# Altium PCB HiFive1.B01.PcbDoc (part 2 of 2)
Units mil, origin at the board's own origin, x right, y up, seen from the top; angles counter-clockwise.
Board outline 2700 x 2100 mil, 2 copper layers (Top Layer, Bottom Layer), stack 61 mil thick; 112 components, 78 nets, 451 pads, 247 vias.
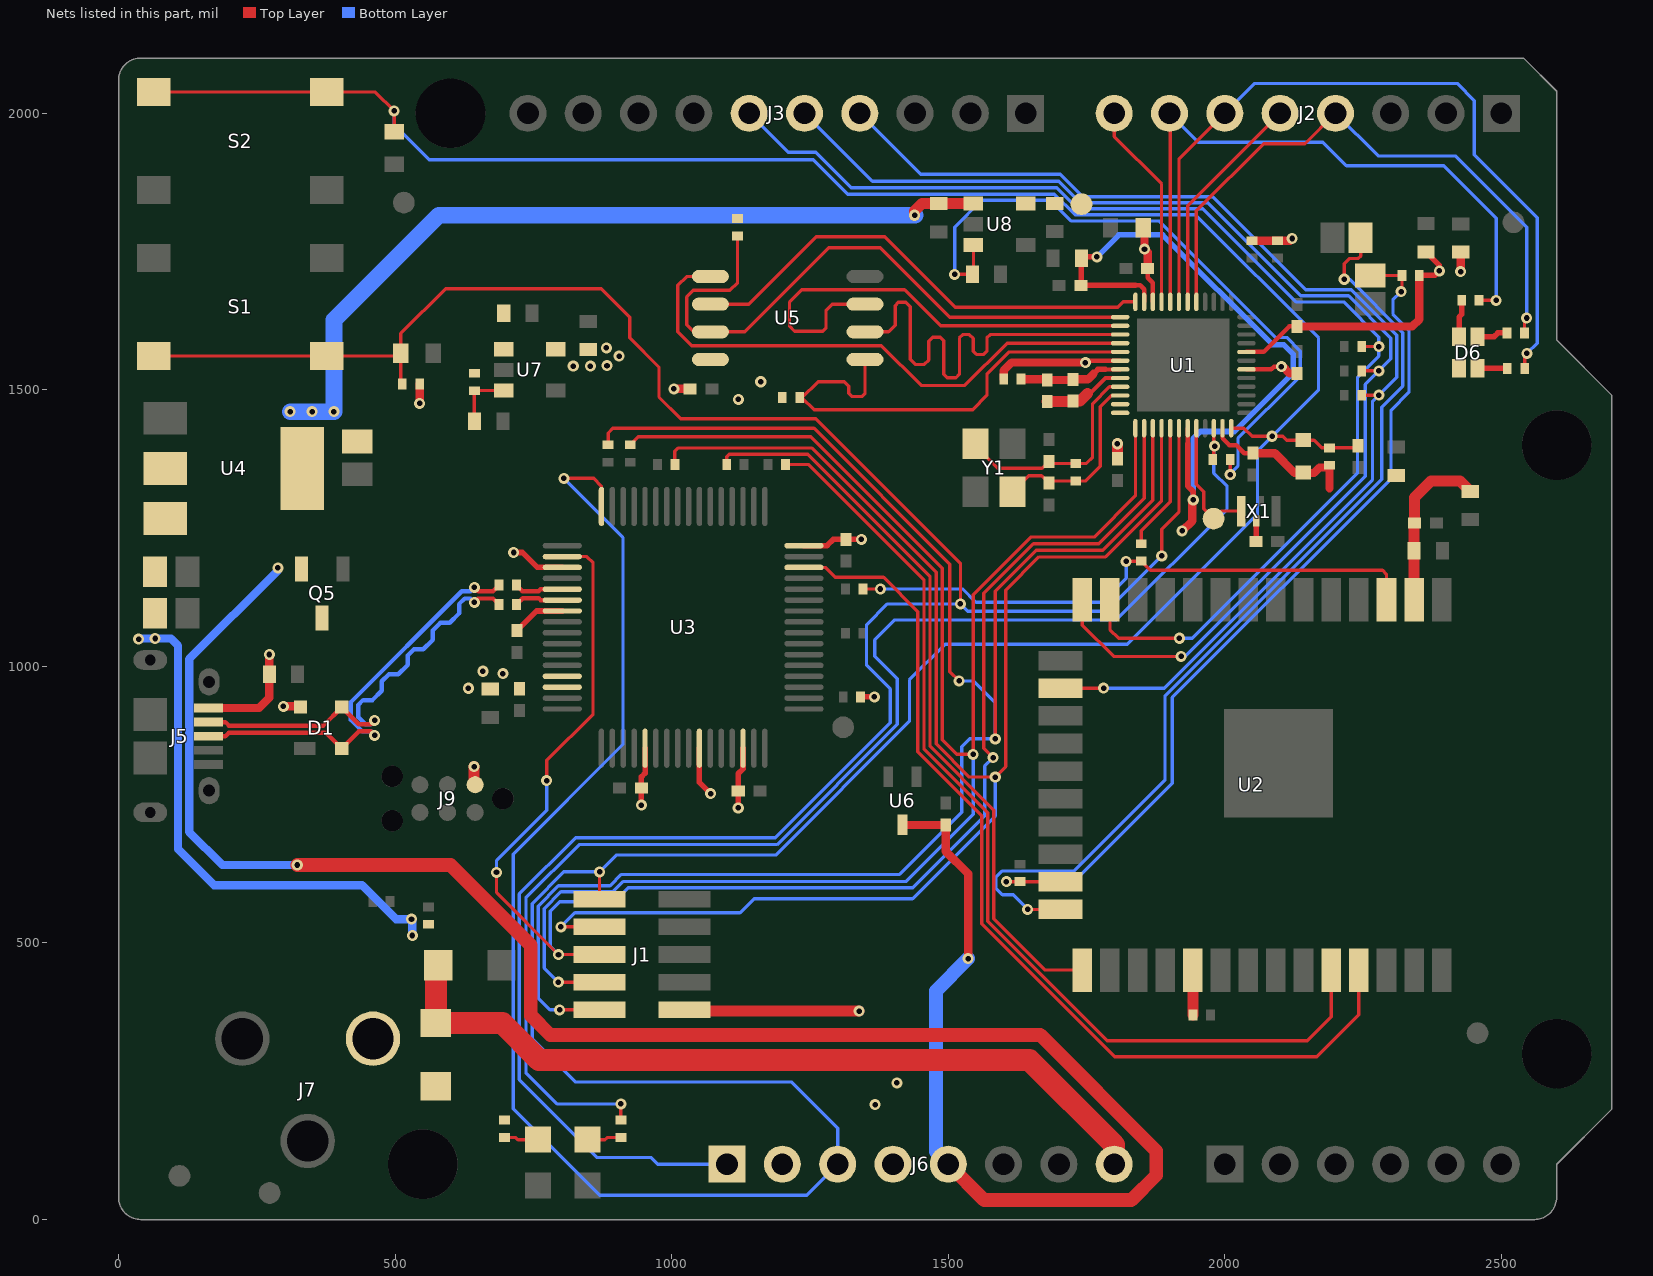
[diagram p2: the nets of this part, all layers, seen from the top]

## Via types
v1: diameter 20, hole 10, Top Layer to Bottom Layer, tented both sides, 229 vias
v2: diameter 20, hole 10.1, Top Layer to Bottom Layer, tented both sides, 18 vias

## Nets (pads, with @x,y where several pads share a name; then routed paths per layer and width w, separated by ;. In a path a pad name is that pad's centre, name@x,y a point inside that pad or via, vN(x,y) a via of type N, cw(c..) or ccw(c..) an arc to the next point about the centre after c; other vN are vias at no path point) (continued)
GPIO_19: J2.4 R18.2 U1.41 | length 1112.7
  Top Layer w6: U1.41@1948.62,1659.17 1948.62,1823.62 2070,1945 2145,1945 J2.4@2200,2000 ; R18.2@2541.75,1603 2541.75,1626.06 v1(2545.69,1630)
  Bottom Layer w6: J2.4@2200,2000 2277,1923 2417,1923 2545.69,1794.31 v1(2545.69,1630)
GPIO_20: J2.5 U1.42 | length 410.1
  Top Layer w6: U1.42@1932.87,1659.17 1932.87,1832.87 J2.5@2100,2000
GPIO_21: J2.6 R17.2 U1.43 | length 1401.7
  Top Layer w6: U1.43@1917.13,1659.17 1917.13,1917.13 J2.6@2000,2000 ; R17.2@2542.28,1539 2542.28,1562.06 v1(2546.22,1566)
  Bottom Layer w6: J2.6@2000,2000 2054,2054 2420,2054 2451,2023 2451,1925 2564.69,1811.31 2564.69,1584.46 v1(2546.22,1566)
GPIO_22: J2.7 R19.2 U1.44 | length 1186
  Top Layer w6: J2.7@1900,2000 1901.38,1998.62 U1.44@1901.38,1659.17 ; R19.2@2463.69,1662 v1(2490.69,1662)
  Bottom Layer w6: J2.7@1900,2000 1952,1948 2177,1948 2220,1905 2396,1905 2490.69,1810.31 v1(2490.69,1662)
GPIO_23: J2.8 U1.45 | length 376.3
  Top Layer w6: J2.8@1800,2000 1800,1958 1885.63,1872.37 U1.45@1885.63,1659.17
JTAG_TCK: J1.4 R25.2 U1.13 | length 2996.5
  Top Layer w6: v1(795.17,429.12) J1.4@869.57,429.12 ; R25.2@925,1400.75 939.27,1415.02 1251.73,1415.02 1489,1177.75 1489,867.2 1515.2,841 v1(1545,841) 1545,1130 1649,1234 1764,1234 1838.39,1308.39 U1.13@1838.39,1430.83
  Bottom Layer w6: v1(795.17,429.12) 769.61,454.68 769.61,562.21 799.8,592.4 893.11,592.4 911.81,611.1 1423.14,611.1 1545,732.96 v1(1545,841)
JTAG_TDI: J1.8 R24.2 U1.16 | length 2869.1
  Top Layer w6: v1(799.61,529.12) J1.8@869.57,529.12 ; R24.2@1005.75,1365 1005.75,1389.31 1011.28,1394.84 1253.8,1394.84 1478,1170.64 1478,859.92 1537.92,800 v1(1585,800) 1604,819 1604,1138.09 1663.91,1198 1784.46,1198 1885.63,1299.17 U1.16@1885.63,1430.83
  Bottom Layer w6: v1(799.61,529.12) 825.02,554.52 1123.48,554.52 1148.94,579.98 1435.5,579.98 1585,729.48 v1(1585,800)
JTAG_TDO: J1.6 U1.14 U3.2 | length 2806.2
  Top Layer w6: v1(683.22,627.52) 683.22,591.2 v1(795.3,479.12) J1.6@869.57,479.12 ; v1(773.81,793.39) 774.32,793.91 774.32,830.31 857.69,913.68 857.69,1187.4 846.42,1198.66 U3.2@802.13,1198.66 ; v1(1581,835) 1564,852 1564,1132.03 1653.97,1222 1772,1222 1854.13,1304.13 U1.14@1854.13,1430.83
  Bottom Layer w6: v1(683.22,627.52) 683.22,649.22 773.81,739.81 v1(773.81,793.39) ; v1(795.3,479.12) 780.61,493.81 780.61,557.65 797.71,574.75 895.63,574.75 920.98,600.1 1436.02,600.1 1566,730.08 1566,820 v1(1581,835)
JTAG_TMS: J1.2 R26.2 U1.15 | length 3162.7
  Top Layer w6: v1(797.34,379.12) J1.2@869.57,379.12 ; R26.2@885,1404.69 885,1422.05 893.4,1430.45 1257.32,1430.45 1502.87,1184.91 1502.87,990.46 v1(1519.53,973.81) ; v1(1585,869) 1585,1136.06 1658.94,1210 1779.49,1210 1869.88,1300.4 U1.15@1869.88,1430.83
  Bottom Layer w6: v1(797.34,379.12) 779.81,379.12 758.61,400.32 758.61,566.76 795.24,603.4 888.55,603.4 909.05,623.9 1411.9,623.9 1524.5,736.5 1524.5,854.5 1539,869 v1(1585,869) 1585,933.91 1545.11,973.81 v1(1519.53,973.81)
LF_CLK: TP5.1 U1.20 X1.3 | length 232.3
  Top Layer w6: U1.20@1948.62,1430.83 1948.62,1409 1948.38,1408.76 1948.38,1329.21 1962,1315.59 1962,1284.89 TP5.1@1979.74,1267.16 1993.57,1281 X1.3@2029.5,1281
NetC8_1: C8.1 C9.1 U1.8 | length 149.5
  Top Layer w7: 1752.08,1493.26 1756.43,1493.26 1784.55,1521.38 U1.8@1810.83,1521.38
  Top Layer w20: C8.1@1678.99,1478.69 1724.83,1478.69 C9.1@1725.83,1479.69 1738.51,1479.69 1752.08,1493.26
NetC12_1: C12.1 R4.1 U1.9 Y1.1 | length 402.2
  Top Layer w6: Y1.1@1549.54,1402.31 1549.54,1398.75 1589.7,1358.59 1669.57,1358.59 C12.1@1681.83,1370.84 1685.76,1366.91 R4.1@1730.45,1366.91 1749.33,1366.91 1760.83,1378.4 1760.83,1475.02 1791.43,1505.63 U1.9@1810.83,1505.63
NetC13_1: C13.1 R4.2 U1.10 Y1.3 | length 338
  Top Layer w6: Y1.3@1616.46,1315.69 1645.36,1344.59 1668.71,1344.59 1678.94,1334.36 1679.99,1335.41 R4.2@1730.45,1335.41 1748.67,1335.41 1775,1361.74 1775,1469.4 1795.48,1489.88 U1.10@1810.83,1489.88
NetC21_1: C21.1 R31.1 U7.3 | length 108.7
  Top Layer w6: C21.1@643.41,1443 643.18,1443.22 R31.1@643.18,1498.66 643.29,1498.77 U7.3@696.11,1498.77
NetC22_1: C22.1 R32.2 U8.3 | length 1232.6
  Top Layer w6: v1(1511.46,1708.88) C22.1@1543.58,1708.88 1545.48,1710.78 U8.3@1545.48,1761.99 ; R32.2@2009.75,1374 2009.85,1373.9 v1(2009.85,1346.79)
  Bottom Layer w6: v1(1511.46,1708.88) 1511.46,1794.35 1560.11,1843 1684.17,1843 1721.79,1805.38 1880.73,1805.38 2091.36,1594.75 2111.79,1594.75 2136.47,1570.07 2136.47,1525.38 2129.77,1518.68 ; v1(2009.85,1346.79) 2009.85,1348.35 2023.75,1362.25 2023.75,1412.18 2130.01,1518.44
NetD6_1: D6.1 R19.1 | length 67.9
  Top Layer w10: D6.1@2423.54,1596.09 2423.54,1631.68 2428.25,1636.39 R19.1@2428.25,1662
NetD6_2: D6.2 R18.1 | length 56.1
  Top Layer w10: D6.2@2457,1596.09 2486.84,1596.09 2493.75,1603 R18.1@2510.25,1603
NetD6_3: D6.3 R17.1 | length 49.9
  Top Layer w10: D6.3@2457,1539 R17.1@2506.85,1539
NetD9_2: D9.2 R27.2 | length 61.6
  Top Layer w6: R27.2@698,148.28 718.03,148.28 721.97,144.34 D9.2@758,144.34
NetD10_2: D10.2 R28.2 | length 61.6
  Top Layer w6: D10.2@848,144.34 879.22,144.34 883.16,148.28 R28.2@908,148.28
NetD13_2: D13.2 J7.1
NetR12_2: R12.2 U2.29 | length 81
  Top Layer w20: R12.2@1942.28,370 U2.29@1942.28,450.98
PLL_AVDD: C8.2 C9.2 R1.2 U1.7 | length 183.8
  Top Layer w7: 1784.13,1537.13 U1.7@1810.83,1537.13
  Top Layer w10: 1762.44,1529.11 1770.45,1537.13 1784.13,1537.13
  Top Layer w15: R1.2@1635.51,1519.37 1677.67,1519.37 C8.2@1678.99,1518.06 1724.83,1518.06 C9.2@1725.83,1519.06 1752.38,1519.06 1762.44,1529.11
QSPI_CS0: R13.1 U1.5 U5.1 | length 858.8
  Top Layer w6: U5.1@1349.53,1555 1349.53,1493.53 1344,1488 1326,1488 1320,1494 1320,1507 1312,1515 1264.51,1515 1235.45,1485.93 1257.35,1464.03 1544.03,1464.03 1570,1490 1570,1528.2 1610.42,1568.62 U1.5@1810.83,1568.62
QSPI_DQ0: U1.4 U5.5 | length 1021.3
  Top Layer w6: U5.5@1070,1705 1027,1705 1011,1689 1011,1605 1036,1580 1379,1580 1451,1508 1530,1508 1606.37,1584.37 U1.4@1810.83,1584.37
QSPI_DQ1: U1.3 U5.2 | length 841.2
  Top Layer w6: U5.2@1349.53,1605 1392,1605 1404,1617 1404,1652.48 1409.72,1658.19 1423.41,1658.19 1431,1650.61 1431,1555 1440,1546 1457,1546 1465,1554 1465,1588.12 1472,1595.12 1485.88,1595.12 1492,1589 1492,1528 1498,1522 1514,1522 1520.26,1528.26 1520.26,1593.9 1526.48,1600.12 1537.88,1600.12 1545,1593 1545,1570 1551,1564 1564,1564 1570,1570 1570,1594 1576.12,1600.12 U1.3@1810.83,1600.12
QSPI_DQ2: U1.2 U5.3 | length 857.2
  Top Layer w6: U5.3@1349.53,1655 1290,1655 1279,1644 1279,1612 1273,1606 1222,1606 1213,1615 1213,1659 1235,1681 1421,1681 1486.13,1615.87 U1.2@1810.83,1615.87
QSPI_DQ3: R29.2 U1.1 U5.7 | length 1141.1
  Top Layer w6: R29.2@1119,1778.25 1119,1694 1105,1680 1039,1680 1027,1668 1027,1618 1040,1605 U5.7@1070,1605 1132,1605 1284,1757 1377,1757 1502.39,1631.61 U1.1@1810.83,1631.61
QSPI_SCK: U1.48 U5.6 | length 876
  Top Layer w6: U5.6@1070,1655 1139,1655 1261,1777 1385,1777 1512.76,1649.24 1806.24,1649.24 1816.17,1659.17 U1.48@1838.39,1659.17
RESET: C16.1 D3.2 D5.1 J1.10 J6.3 R5.1 S2.3 S2.4 U1.24 U3.64 | length 7629.2
  Top Layer w6: S2.4@63.5,2038.58 S2.3@376.5,2038.58 464.05,2038.58 v1(498.06,2004.57) D5.1@498.06,1966.92 ; v1(805,1340) 859,1340 872.99,1326.01 U3.64@872.99,1289.21 ; J1.10@869.57,579.12 v1(869.57,628.57) ; U1.24@2011.61,1430.83 2034.54,1430.83 2049.21,1416.16 v1(2085.71,1416.16) 2104.86,1416.16 2112.12,1408.9 2161.3,1408.9 2175.08,1395.12 R5.1@2189.32,1395.12 2236.89,1395.12 C16.1@2240.83,1399.06
  Bottom Layer w6: v1(498.06,2004.57) 498.06,1979.43 561.31,1916.18 1255.82,1916.18 1318,1854 1691.85,1854 1729.47,1816.38 1946.94,1816.38 2169.47,1593.85 2169.47,1499.92 v1(2085.71,1416.16) 2059,1389.45 2059,1275 1824,1040 1494.29,1040 1429.91,975.62 1429.91,900.78 1188.13,659 900,659 v1(869.57,628.57) 804.86,628.57 747.61,571.32 747.61,326.76 825.61,248.76 1216.05,248.76 1300,164.82 J6.3@1300,100 1244,44 869.48,44 713.4,200.08 713.4,660.4 911.85,858.85 911.85,1233.15 v1(805,1340)
SPI_CS2: R10.1 R21.2 SJ1.2 U2.23 | length 1639.3
  Top Layer w6: v1(1605,611) 1605.37,610.63 U2.23@1702.91,610.63 ; SJ1.2@2262.83,1706.96 R10.1@2316.32,1706.96 ; v1(2318.61,1677.5) 2320.25,1679.14 R10.1@2320.25,1706.96
  Bottom Layer w6: v1(1605,611) 1727,611 1905,789 1905,943.88 2300.51,1339.39 2300.51,1463.51 2333,1496 2333,1608.13 2304,1637.13 2304,1662.89 v1(2318.61,1677.5)
SPI_MISO: J3.5 R15.1 U2.14 | length 2240
  Top Layer w6: U2.14@1742.28,1120.28 1742.28,1074.72 1799,1018 v1(1921,1018) ; R15.1@2251.51,1534.37 v1(2278.51,1534.37)
  Bottom Layer w6: J3.5@1240,2000 1362.96,1877.04 1699.92,1877.04 1738.59,1838.38 1969.06,1838.38 2137.44,1670 2223.77,1670 2300,1593.77 2300,1555.86 v1(2278.51,1534.37) 2254,1509.86 2254,1343.79 1928.21,1018 v1(1921,1018)
SPI_MOSI: J3.4 R9.1 U2.16 | length 2164.3
  Top Layer w6: U2.16@1702.91,960.63 v1(1781,960.63) ; R9.1@2251.51,1490.37 v1(2278.51,1490.37)
  Bottom Layer w6: J3.4@1340,2000 1450.02,1889.98 1702.55,1889.98 1743.14,1849.38 1977.86,1849.38 2146.24,1681 2229.02,1681 2311,1599.02 2311,1522.86 v1(2278.51,1490.37) 2267,1478.86 2267,1336.99 1890.64,960.63 v1(1781,960.63)
SPI_SCK: J3.6 R16.1 U2.13 | length 2226.1
  Top Layer w6: U2.13@1792.28,1120.28 1792.28,1066.72 1808,1051 v1(1918,1051) ; R16.1@2251.51,1578.37 v1(2278.51,1578.37)
  Bottom Layer w6: J3.6@1140,2000 1210.5,1929.5 1260.5,1929.5 1324.6,1865.4 1696.01,1865.4 1734.03,1827.38 1960.26,1827.38 2100.41,1687.23 2128.64,1659 2214.97,1659 2278.51,1595.46 v1(2278.51,1578.37) 2278.51,1561.24 2240,1522.73 2240,1350 1941,1051 v1(1918,1051)
USB_D_N: D1.3 J5.2 R2.1 | length 777.6
  Top Layer w8: J5.2@162.5,899.41 193.07,899.41 199.37,893.11 370.24,893.11 D1.3@403.46,926.33 434.36,895.43 455.96,895.43 v1(462.96,902.43) ; v1(643.21,1115.89) 643.21,1116.39 649.71,1122.89 676.88,1122.89 R2.1@687.88,1111.89
  Bottom Layer w8: v1(462.96,902.43) 455.96,895.43 446.1,895.43 433.05,908.48 433.05,930.25 442,939.2 458.99,939.2 475.76,955.97 475.76,972.96 488.8,986 505.79,986 522.56,1002.77 522.56,1019.76 534,1031.2 550.99,1031.2 567.76,1047.97 567.76,1064.96 581.8,1079 598.79,1079 615.56,1095.77 615.56,1112.76 625.69,1122.89 636.21,1122.89 v1(643.21,1115.89)
USB_D_P: D1.2 J5.3 R6.1 | length 778.6
  Top Layer w8: J5.3@162.5,873.82 193.07,873.82 199.37,880.11 374.87,880.11 D1.2@403.46,851.53 434.36,882.43 455.96,882.43 v1(462.96,875.43) ; v1(643.21,1142.89) 650.21,1135.89 676.88,1135.89 R6.1@687.88,1146.89
  Bottom Layer w8: v1(462.96,875.43) 455.96,882.43 440.72,882.43 420.05,903.1 420.05,935.64 620.3,1135.89 636.21,1135.89 v1(643.21,1142.89)
USB_D_R_N: R2.2 U3.6 | length 88.8
  Top Layer w8: R2.2@719.38,1111.89 730.75,1123.26 759.35,1123.26 762.69,1119.92 U3.6@802.13,1119.92
USB_D_R_P: R6.2 U3.5 | length 88.5
  Top Layer w8: R6.2@719.38,1146.89 730,1136.26 759.35,1136.26 762.69,1139.61 U3.5@802.13,1139.61
VBUS: C29.2 D1.4 J5.1 Q5.3 | length 227.2
  Top Layer w15: J5.1@162.5,925 254,925 272.41,943.41 C29.2@272.41,986 v1(272.41,1021.59) ; v1(297.83,927.83) 327.15,927.83 D1.4@328.65,926.33
VDD_1V8: C1.1 C2.2 C3.2 C50.1 R1.1 TP1.1 U1.6 U1.30 U1.46 U8.5 | length 473.4
  Top Layer w8: v1(1747.83,1549.37) 1751.33,1552.87 U1.6@1810.83,1552.87 ; C2.2@1860.51,1719.37 1860.51,1702.87 1869.88,1693.5 U1.46@1869.88,1659.17 ; U1.30@2039.17,1537.13 2084.13,1537.13 2089,1542 v1(2102.47,1542)
  Top Layer w15: R1.1@1600.08,1519.37 1600.08,1534.73 1614.72,1549.37 v1(1747.83,1549.37) ; C1.1@1852.53,1793 1854.83,1790.7 v1(1854.83,1754.37) 1860.51,1748.69 C2.2@1860.51,1719.37 ; v1(2102.47,1542) 2105,1542 2117.32,1529.68 C3.2@2130.83,1529.68
VDD_3V3: C4.2 C5.2 C6.1 C7.1 C10.1 C11.1 C14.1 C15.1 C17.2 C18.2 C19.2 C20.2 C23.2 C24.1 C25.1 C26.1 C27.1 C28.2 C30.1 C47.1 D3.1 D6.4 J1.1 J6.2 J6.4 J9.1 R3.1 R5.2 R7.2 R8.2 R10.2 R13.2 R27.1 R29.1 R33.1 U1.11 U1.12 U1.19 U1.23 U1.32 U1.47 U2.2 U3.3 U3.7 U3.13 U3.14 U3.21 U3.26 U3.30 U3.48 U5.8 U7.5 X1.4 | length 3563.5
  Top Layer w8: 1838,1689 1846.91,1689 1854.13,1681.78 U1.47@1854.13,1659.17 ; 1932.87,1402.62 U1.19@1932.87,1430.83 ; U1.23@1995.87,1430.83 1995.87,1412.71 2008.29,1400.29 2020.71,1400.29 2035.32,1385.68 C5.2@2051,1385.69 ; U1.32@2039.17,1568.62 2070.59,1568.62 2116.66,1614.69 C18.2@2130.83,1614.68
  Top Layer w10: v1(714,1206) 730,1206 757.02,1178.98 U3.3@802.13,1178.98 ; C30.1@720,1064.68 755.55,1100.24 U3.7@802.13,1100.24 ; v1(945,749.22) C27.1@945,780 945,800.22 951.73,806.95 U3.21@951.73,852.2 ; U3.26@1050.16,852.2 1050.16,790.3 v1(1070.24,770.22) ; v1(1120.32,744.08) C26.1@1120.32,775 1120.32,806.08 1128.9,814.66 U3.30@1128.9,852.2 ; U3.48@1239.13,1218.35 1280.73,1218.35 1292.07,1229.68 C24.1@1315,1229.68 v1(1342.95,1229.68) ; R33.1@1341.5,945 v1(1366.31,945) ; v1@1769.22,1740.55 v1(1768.81,1740.55) 1743.14,1740.55 C10.1@1740.59,1738 1740.59,1689.91 C20.2@1739.69,1689 1838,1689 ; 1932.87,1402.62 1932.87,1326.33 1943,1316.2 v1(1943,1301) ; C17.2@2056.31,1226 2057.06,1226.75 X1.4@2057.06,1263.28 ; R10.2@2355.69,1706.96 2379.96,1706.96 v1(2388,1715) 2388,1725.2 C14.1@2363.8,1749.41
  Top Layer w15: v1(544.28,1475.72) R3.1@544.28,1511 ; v1(1003.76,1501.75) 1003.95,1501.93 C23.2@1033.08,1501.93 ; v1(1923,1245) 1941.31,1263.31 1941.31,1299.31 v1(1943,1301) ; R8.2@2049.01,1769.8 R7.2@2095.51,1769.8 2117.8,1769.8 v1(2121.74,1773.74) ; C5.2@2051,1385.69 2090.32,1385.68 2126.16,1349.84 D3.1@2138.56,1349.84 ; C18.2@2130.83,1614.68 2338.78,1614.69 2351.75,1627.65 R10.2@2351.75,1706.96 ; D3.1@2140.83,1347.58 D3.1@2138.56,1349.84 ; 2189.32,1322 2189.32,1359.68 2171.14,1359.68 2161.3,1349.84 D3.1@2138.56,1349.84 ; v1(2426.52,1713.87) C15.1@2426.52,1749.07
  Top Layer w20: v1(642.78,818.89) 642.78,787.99 J9.1@644.65,786.11 ; J1.1@1023.11,379.12 1025.4,376.83 v1(1338.74,376.83) ; C19.2@1805.83,1375.54 v1(1805.83,1402.62) ; U2.2@2342.28,1120.28 C6.1@2342.28,1209.1 2342.28,1258.2 C4.2@2343.18,1259.1 2343.18,1305.18 2373,1335 2425.59,1335 C7.1@2444,1316.59
  Bottom Layer w10: v1(1768.81,1740.55) 1808.47,1780.22 1887.51,1780.22 2085.97,1581.75 2106.4,1581.75 2123.47,1564.69 2123.47,1530.77 2017.48,1424.78 1956.08,1424.78 1943,1411.7 v1(1943,1301)
  other v1: 1367.8,207.86 1407.01,247.17 632.29,960.59 694.87,987.17 658.54,991.27 1120.69,1482.91 1160.97,1514.77 822,1543 853,1543 883,1544 905,1561 882,1576
VDD_5V0: C31.1 C42.1 C45.1 C48.1 J6.5 Q5.2 R31.2 U4.2 U4.4 U6.3 U7.1 U8.1 | length 5306.9
  Top Layer w15: U6.3@1417.21,714.02 1417.81,713.41 C31.1@1495.46,713.41 1495.46,665.75 1535.97,625.23 v1(1535.97,471.74)
  Top Layer w20: v1(1439.3,1815.71) 1439.3,1823.58 1452.44,1836.72 C48.1@1482.63,1836.72 1482.71,1836.8 U8.1@1545.48,1836.8
  Top Layer w25: v1(323,641) 600,641 745.27,495.73 745.27,368.66 780.31,333.61 1666.39,333.61 1876,124 1876,80 1831,35 1565,35 J6.5@1500,100
  Bottom Layer w15: v1(288,1178) 288,1173.5 127.5,1013 127.5,701 187.5,641 v1(323,641)
  Bottom Layer w25: J6.5@1500,100 1477.61,122.39 1477.61,413.38 v1(1535.97,471.74)
  Bottom Layer w30: v1(310,1460.64) v1(349.66,1460.64) v1(389.32,1460.64) 389.32,1626.32 579,1816 v1@1440,1816
VDD_CORE_EN: R28.1 R32.1 U1.22 | length 2420.8
  Top Layer w6: R28.1@908,183.71 v1(908,209) ; R32.1@1980,1378.75 1980,1398.88 1980.12,1399 U1.22@1980.12,1430.83
  Bottom Layer w6: v1(908,209) 792.48,209 736.53,264.95 736.53,582.07 832.45,678 1190.43,678 1407.65,895.22 1407.65,978.07 1367.22,1018.49 1367.22,1047.85 1403.37,1084 1803.5,1084 2004,1284.5 2004,1325.77 1980.12,1349.65 1980.12,1399 1980.62,1398.5 v1(1981.5,1398.5) 1981.5,1398.81 v1@1981.69,1399
VDD_DCIN: C43.1 C44.1 D12.1 D13.1 J6.8 R30.2 U4.3 | length 2414.1
  Top Layer w20: D12.1@575.23,459.37 D12.1@580,464.14
  Top Layer w40: D12.1@575.23,459.37 573.58,457.72 D13.1@573.58,355.19 693.52,355.19 760.15,288.56 1646.44,288.56 1800,135 J6.8@1800,100
  Bottom Layer w15: v1(36,1049.5) 37,1050.5 v1(66,1050.5) 94.5,1050.5 107.5,1037.5 107.5,669.5 172.5,604.5 440,604.5 501.5,543 v1(529.5,543) 531,541.5 v1(531,513.5)
WAKE: D2.1 J6.1 R3.2 S1.1 S1.2 U1.18 | length 4547
  Top Layer w6: S1.2@63.5,1561.42 S1.1@376.5,1561.42 505.42,1561.42 D2.1@510,1566 ; R3.2@508.84,1511 510,1512.16 D2.1@510,1566 ; J6.1@1085.32,114.69 J6.1@1100,100 ; v1(1522,1113) 1522,1186.41 1260.41,1448 1016,1448 977,1487 977,1541 924,1594 924,1631.58 872.56,1683.02 591.02,1683.02 510,1602 D2.1@510,1566 ; v1(1886,1200) 1886,1248 1917.13,1279.13 U1.18@1917.13,1430.83
  Bottom Layer w6: J6.1@1100,100 975,100 963.03,111.97 865.55,111.97 724.4,253.12 724.4,588.61 826.22,690.43 1187.3,690.43 1395.07,898.2 1395.07,959.27 1352.28,1002.05 1352.28,1075.28 1390,1113 v1(1522,1113) 1535,1100 1786,1100 v1(1886,1200)
WF_BOOT_STRAP: R23.2 U2.25 | length 1340.6
  Top Layer w6: R23.2@1099.25,1365 1099.25,1379.44 1103.66,1383.84 1245.74,1383.84 1467,1162.58 1467,855.36 1582.48,739.88 1582.48,543.63 1675.13,450.98 U2.25@1742.28,450.98
WF_INT: SJ2.2 U2.24 | length 1760.8
  Top Layer w6: v1(1643.63,560.63) U2.24@1702.91,560.63 ; v1(2216,1700) 2216,1728 2225.61,1737.61 2241.16,1737.61 2245.59,1742.05 SJ2.2@2245.59,1775
  Bottom Layer w6: v1(1643.63,560.63) 1617.26,587 1598,587 1586,599 1586,618.87 1597.13,630 1727.26,630 1891.75,794.49 1891.75,946.18 2284,1338.44 2284,1468.99 2322,1506.99 2322,1603.57 2225.57,1700 v1(2216,1700)
WF_RESET: R20.2 U1.17 | length 226.5
  Top Layer w6: R20.2@1849,1226 1849,1245.16 1901.38,1297.54 U1.17@1901.38,1430.83
WF_RESET_R: R14.2 R20.1 U2.3 | length 1060
  Top Layer w6: R14.2@1345.75,1140 v1(1377.19,1140) ; v1(1821.74,1190.02) 1845.61,1190.02 R20.1@1847.03,1188.6 ; R20.1@1849,1190.57 1865.57,1174 2285.28,1174 2292.28,1167.01 U2.3@2292.28,1120.28
  Bottom Layer w6: v1(1377.19,1140) 1526,1140 1550,1116 1778,1116 1821.74,1159.74 v1(1821.74,1190.02)
WF_UART_RX: R22.2 U2.34 | length 1815.2
  Top Layer w6: R22.2@1205.75,1365 1248.14,1365 1456,1157.14 1456,850.8 1571.48,735.33 1571.48,539.08 1787.56,323 2149,323 2192.28,366.28 U2.34@2192.28,450.98
WF_UART_TX: U2.35 U3.46 | length 1745.1
  Top Layer w6: U3.46@1239.13,1178.98 1277.32,1178.98 1295.3,1161 1383.06,1161 1445,1099.06 1445,845.84 1560.48,730.36 1560.48,534.52 1801,294 2166,294 2242.28,370.28 U2.35@2242.28,450.98
pads on no net: Designator31.1 Designator32.1 Designator33.1 J3.8 J4.1 J5.4 J5.SH4 J5.SH5 J9.SH1 J9.SH2 J9.SH3 U1. U2. U2.4 U2.5 U2.6 U2.7 U2.8 U2.9 U2.10 U2.11 U2.12 U2.17 U2.18 U2.19 U2.20 U2.21 U2.22 U2.26 U2.27 U2.28 U2.30 U2.31 U2.32 U2.33 U2.36 U2.37 U3.1 U3.8 U3.9 U3.10 U3.11 U3.12 U3.17 U3.18 U3.19 U3.20 U3.23 U3.27 U3.28 U3.29 U3.32 U3.33 U3.35 U3.36 U3.37 U3.38 U3.41 U3.42 U3.43 U3.45 U3.51 U3.52 U3.53 U3.54 U3.55 U3.56 U3.57 U3.58 U3.60 U3.61 U7.4 U8.4 X1.1

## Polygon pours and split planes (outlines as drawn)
VDD_3V3 on Top Layer "Bottom Layer-No Net" (solid, remove dead copper, pour order 63): 1181.63,526.4 1181.63,403.12 1225.61,359.15 1278.27,359.61 1378.61,359.61 1396.74,377.74 1396.74,495.7 1139.46,752.97 1135.19,757.24 1135.19,790.36 1129.33,796.23 1045.95,796.23 1042.93,794.93 1040.78,792.78 1040.78,710.88 1041.09,665.43
NetD13_2 on Top Layer "NETD13_2_L01_P048" (solid, remove dead copper, pour order 48): 514.92,300 546.42,268.49 622.98,268.49 635,256.47 635,170 410,170 410,380 514.92,380
VDD_3V3 on Top Layer "Bottom Layer-No Net" (solid, remove dead copper, pour order 50): 700.33,1001.46 695.68,1006.1 695.68,1044.85 702.09,1051.25 730.13,1051.25 732.4,1053.52 732.4,1075.17 725.81,1081.77 670.55,1081.77 619.73,1030.95 619.73,953.58 626.81,946.49 737.97,946.49 748.32,956.84 836.31,956.84 838.75,959.28 838.48,985.68 834.67,989.49 712.46,989.49
VDD_3V3 on Top Layer "Bottom Layer-No Net" (solid, remove dead copper, pour order 55): 770,1591 906,1591 918,1579 918,1535 909,1526 780,1526 768,1538 768,1589
GND on Top Layer "Bottom Layer-No Net" (solid, remove dead copper, pour order 57): 888.81,1611.48 894.86,1617.53 894.86,1650.55 873.2,1672.2 817.38,1672.2 804.12,1658.94 804.12,1620.55 813.19,1611.48
VDD_1V8 on Top Layer "Bottom Layer-No Net" (solid, remove dead copper, pour order 59): 1621.05,1822.65 1709.7,1822.65 1719.06,1813.28 1761.27,1813.28 1770.64,1822.65 1817.36,1822.65 1833.89,1806.11 1833.89,1774.6 1840.44,1768.04 1840.44,1714.05 1847.92,1706.57 1872.28,1706.57 1876.33,1710.62 1876.33,1852.92 1865.41,1863.84 1627.92,1863.84 1619.5,1855.42 1619.5,1824.51 1620.74,1823.27
VDD_3V3 on Top Layer "VDD_3V3_L01_P047" (solid, remove dead copper, pour order 47): 1790.83,1479.37 1830.83,1479.37 1830.83,1394.37 1830.83,1354.37 1790.83,1354.37 1790.83,1389.37
GND on Top Layer "Bottom Layer-No Net" (solid, remove dead copper, pour order 53): 835.2,947.92 837.81,945.31 837.81,888.81 819.24,870.23 658.12,870.23 652.66,875.69 652.66,920.28 654.79,922.41 698.39,922.41 710.55,934.58 747.74,934.58 761.09,947.92
VDD_3V3 on Top Layer "VDD_3V3_L01_P040" (solid, remove dead copper, pour order 40): 1435,247.92 1423.4,259.52 672.61,259.52 658,245.17 658,180 668,170 709,170 709,171 760.98,222.98 944.56,222.98 977,190.54 977,108 1042,43 1151,43 1406,43 1435,72
VDD_5V0 on Top Layer "VDD_5V0_L01_P036" (solid, remove dead copper, pour order 36): 624.1,1515.57 630.56,1522.03 652.04,1522.03 654.36,1524.35 654.36,1554.24 660.45,1560.34 711.24,1560.34 717,1565.99 717,1652 705,1664 623.18,1664 611.34,1652.16 611.34,1557.69 572.28,1517.25 572.28,1499.34 560.93,1488 270,1488 174,1392 44,1392 41,1389 41,1319 45,1315 136,1315 141,1310 141,1292 281,1152 355,1152 377,1174 377,1301 377,1364 398,1385 546,1385 623.26,1462.26 624.1,1461.95
VDD_3V3 on Top Layer "VDD_3V3_L01_P046" (solid, remove dead copper, pour order 46): 1101.76,1801 1089.07,1788.31 1089.07,1742.3 1075.32,1728.55 1029.83,1728.55 994,1692.59 994,1601 1028,1567 1105,1567 1137,1535 1188,1535 1211,1512 1211,1464 1206,1459 1070,1459 1056,1473 1056,1521.93 1048.93,1529 1011,1529 941,1599 941,1827 1018,1904 1139.12,1904 1146.87,1896.54 1146.87,1816.7 1131.17,1801
VDD_3V3 on Top Layer "VDD_3V3_L01_P044" (solid, remove dead copper, pour order 44): 1912,1201 1912,1260 1928,1276 1981,1276 1997,1260 1997,1252 2008,1241 2009,1240 2029,1240 2039,1240 2045,1246 2047,1248 2047,1259 2047,1273 2050,1276 2052,1278 2061,1278 2063,1278 2067,1274 2070,1271 2070,1223 2070,1213 2075,1208 2076,1207 2106,1207 2126,1207 2144,1225 2144,1260 2144,1320 2092,1372 2026,1372 2019,1372 2015,1376 2015,1399 2018,1402 2081,1402 2091,1392 2108,1375 2179,1375 2197,1375 2197,1320 2206,1311 2242,1311 2294,1363 2329,1363 2438,1363 2457,1382 2457,1473 2446,1484 2441,1489 2367,1489 2342,1514 2339,1517 2339,1640 2339,1754 2348,1763 2350,1765 2379,1765 2393,1765 2404,1754 2404,1677 2404,1566 2408,1562 2410,1560 2425,1560 2429,1560 2434,1555 2433,1554 2433,1530 2433,1517 2437,1513 2481,1513 2486,1513 2499,1500 2499,1347 2463,1311 2382,1311 2358,1287 2358,1236 2358,1177.59 2293.95,1179.05 2286,1187 2210,1187 2199,1187 1926,1187
VBUS on Top Layer "VBUS_L01_P039" (solid, remove dead copper, pour order 39): 259.96,918 269.97,907.98 335.27,907.98 340.49,913.21 340.49,941.03 331.47,950.06 300.79,950.06 290.04,960.67 289.07,1007.87 299.2,1018 359,1018 383,1042 383,1108 378,1113 293.49,1113 253.46,1072.97 253.46,949.69 241.44,937.66 184.56,937.66 179.7,932.8 179.7,919.37 181.7,918
VDD_DCIN on Top Layer "a" (solid, remove dead copper, pour order 67): 612.5,530 600.5,542 549.5,542 535.5,556 515,556 505,546 505,365.5 544,326.5 602,326.5 612.5,337
VDD_DCIN on Top Layer "a" (solid, pour order 69): 45,1302.5 127.5,1302.5 136,1294 136,1239 120,1223 104.5,1223 93,1211.5 93,1050.86 78.22,1036.08 33.92,1036.08 21,1049 21,1290.5 32,1301.5 45,1301.5
GND on Top Layer "GND_L01_P071" (solid, remove dead copper, pour order 71): 2525,2080 30,2080 20,2070 10,2060 10,2040 10,35 35,10 100,10 2550,10 2575,35 2585,45 2585,85 2585,110 2605,130 2690,215 2690,390 2690,1480 2605,1565 2590,1580 2590,1790 2590,2015 2525,2080
VDD_3V3 on Bottom Layer "VDD_3V3_L02_P043" (solid, remove dead copper, pour order 43): 2397.64,1825 2440.08,1782.57 2440.08,1708.2 2433.42,1701.55 2381.08,1701.55 2377.31,1706 2377,1706 2328,1755 2319,1764 2161,1764 2152,1755 2116,1755 2106,1765 2106,1795 2136,1825
VDD_3V3 on Bottom Layer "Bottom Layer-No Net" (solid, remove dead copper, pour order 65): 1421.76,405.81 1453.08,374.49 1453.08,79.18 1453.88,77.3 1453.88,62.48 1437.74,46.34 1370.59,46.34 1346.19,70.74 1346.19,136.26 1213.32,269.13 1073.68,269.13 1054.44,288.38 1054.44,388.26 1070.01,403.83 1118.57,403.83
VDD_3V3 on Bottom Layer "VDD_3V3_L02_P045" (solid, remove dead copper, pour order 45): 670.04,932.31 648.9,911.17 648.9,861.05 665.4,844.56 665.4,813.25 647.52,795.37 611.89,795.37 583.21,824.05 583.21,946.36 620.07,986.51 639.6,1006.04 758.04,1006.04 790.06,1038.06 790.06,1164.94 762.48,1192.52 554.48,1192.52 532,1215 532,1509 555,1532 680.47,1532 738.47,1590 1101,1590 1135.46,1555.54 1267,1424 1342.74,1424 1774,1424 1884,1424 1956,1352 1956,1258 1929,1231 1907,1231 1785,1353 1458.41,1353 1369.14,1263.73 1369.14,1172.77 1341.2,1144.82 1341.2,994.99 1378.46,957.72 1378.46,890.97 1349.73,862.24 1301.6,862.24 1283.75,844.39 1283.75,795.49 1158.78,670.51 963.94,670.51 927.45,706.99 927.45,759 935.22,766.78 1030.7,766.78 1275.45,1011.52 1275.45,1261.63 1173,1353 1138,1388 1097.02,1428.98 1096.89,1430.81 1096.89,1483.88 1082.79,1497.99 1060.19,1497.99 1044.41,1482.21 1043.79,1482.21 723.21,1482.21 610,1369 610,1273.77 625.77,1258 802,1258 870.06,1189.94 871.3,1150.02 872,1149.3 872,1068.61 871.53,985.04 818.8,932.31
VDD_1V8 on Bottom Layer "VDD_1V8_L02_P049" (solid, remove dead copper, pour order 49): 1836,1735 1836,1768.33 1850.48,1782.82 1850.48,1784 1887,1784 1904,1767 1904.2,1767 2114.37,1556.82 2117.11,1556.82 2117.11,1521.95 2029.93,1434.77 1741.72,1434.77 1713.76,1462.74 1713.76,1475.6 1713.76,1534.76 1739,1560 1771.61,1560 1780.29,1551.32 1780.29,1505.89 1816.09,1470.1 1983.57,1470.1 1984.48,1469.19 1998.5,1483.21 1998.5,1611.82 1961.31,1649 1935,1649 1921,1650
GND on Bottom Layer "GND_L02_P073" (solid, remove dead copper, pour order 73): 2525,2080 30,2080 20,2070 10,2060 10,2040 10,35 35,10 100,10 2550,10 2575,35 2585,45 2585,85 2585,110 2605,130 2690,215 2690,390 2690,1480 2605,1565 2590,1580 2590,1790 2590,2015 2525,2080

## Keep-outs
Top Layer:
  circle w1: c2457,337 r39.37
  circle w1: c110,79 r39.2
  circle w1: c515.62,1838.64 r39.37
Keep-Out Layer:
  lines w1: 10,40 ccw(c40,40) 40,10 2560,10 ccw(c2560,40) 2590,40 2590,100 2690,200 2690,1490 2590,1590 2590,2040 2540,2090 40,2090 ccw(c40,2060) 10,2060 10,40

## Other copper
Top Layer:
  pour cut-out: 1838.39,1632.17 2011.61,1632.17 2011.61,1457.83 2007.15,1453.37 1838.83,1453.37 1838.83,1631.73
  text "'.Layer_Name'" at 919.03,-400.6 h60
Bottom Layer:
  region net VDD_5V0: 405,1490 305,1490 295,1480 295,1445 310,1430 390,1430 410,1450 410,1485
  text "'.Layer_Name'" at 919.03,-400.6 h60
Multi-Layer:
  pour cut-out: 2409.99,1171 2409.99,404 2690,404 2690,1171

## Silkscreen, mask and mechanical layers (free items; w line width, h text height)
Top Overlay:
  circle w15: c437.91,1830.39 r6
  circle w15: c433.94,1540.11 r6
  text "RESET" at 461.01,1858.06 h60 r90
  text "1.8V" at 1776,1830 h40
  text "GND" at 2501,1750 h40
  text "WAKE" at 460.36,1569.82 h60 r90
  text "WAKE" at 1135.11,168.12 h80 r90
  text "GND" at 309.98,31.79 h40
  text "'.Layer_Name'" at 919.03,-400.6 h60
Bottom Overlay:
  pour cut-out: 1800.04,1966.89 cw(c1800.04,2000.35) 1766.58,2000.35 cw(c1800.04,2000.35) 1800.04,2033.82 cw(c1800.04,2000.35) 1833.51,2000.35 cw(c1800.04,2000.35)
  text "'.Layer_Name'" at 919.03,-400.6 h60
Top Paste:
  text "'.Layer_Name'" at 919.03,-400.6 h60
Bottom Paste:
  text "'.Layer_Name'" at 919.03,-420.6 h60
Top Solder:
  text "'.Layer_Name'" at 919.03,-400.6 h60
Bottom Solder:
  text "'.Layer_Name'" at 919.03,-420.6 h60
Board Outline:
  the board outline again, w20
Fabrication:
  the board outline again, w20
Fabrication (Mech3):
  lines w30: -323.13,-2335.45 -323.13,-2277
Drill Drawing:
  circle w10: c4119.13,283.7 r33.33
  lines w10: 5323.53,1339.59 6173.53,1339.59 ; 5323.53,1439.59 6173.53,1439.59 ; 5323.53,2039.59 6173.53,2039.59 ; 5323.53,2139.59 6173.53,2139.59 ; 5373.53,1639.59 5473.53,1539.59 ; 5373.53,1939.59 5473.53,1839.59 ; 5423.53,1539.59 5323.53,1639.59 ; 5423.53,1639.59 5523.53,1539.59 ; 5423.53,1839.59 5323.53,1939.59 ; 5423.53,1939.59 5523.53,1839.59 ; 5473.53,1639.59 5573.53,1539.59 ; 5473.53,1939.59 5573.53,1839.59 ; 5523.53,1639.59 5623.53,1539.59 ; 5523.53,1939.59 5623.53,1839.59 ; 5573.53,1639.59 5673.53,1539.59 ; 5573.53,1939.59 5673.53,1839.59 ; 5623.53,1639.59 5723.53,1539.59 ; 5623.53,1939.59 5723.53,1839.59 ; 5673.53,1639.59 5773.53,1539.59 ; 5673.53,1939.59 5773.53,1839.59 ; 5723.53,1639.59 5823.53,1539.59 ; 5723.53,1939.59 5823.53,1839.59 ; 5773.53,1639.59 5873.53,1539.59 ; 5773.53,1939.59 5873.53,1839.59 ; 5823.53,1639.59 5923.53,1539.59 ; 5823.53,1939.59 5923.53,1839.59 ; 5873.53,1639.59 5973.53,1539.59 ; 5873.53,1939.59 5973.53,1839.59 ; 5923.53,1639.59 6023.53,1539.59 ; 5923.53,1939.59 6023.53,1839.59 ; 5973.53,1639.59 6073.53,1539.59 ; 5973.53,1939.59 6073.53,1839.59 ; 6023.53,1639.59 6123.53,1539.59 ; 6023.53,1939.59 6123.53,1839.59 ; 6073.53,1639.59 6173.53,1539.59 ; 6073.53,1939.59 6173.53,1839.59 ; 5323.53,1639.59 6173.53,1639.59 6173.53,1589.59 6173.53,1539.59 ; 5323.53,1639.59 5323.53,1589.59 5323.53,1539.59 6173.53,1539.59 ; 5323.53,1939.59 5323.53,1889.59 5323.53,1839.59 6173.53,1839.59 ; 5323.53,1939.59 6173.53,1939.59 6173.53,1889.59 6173.53,1839.59 ; 4085.8,-166.3 4119.13,-199.64 4152.46,-166.3 4119.13,-132.97 4085.8,-166.3 ; 4085.8,17.03 4152.46,17.03 4119.13,-49.64 4085.8,17.03 ; 4085.8,100.36 4152.46,100.36 4152.46,167.03 4085.8,167.03 4085.8,100.36 ; 4085.8,417.03 4102.46,417.03 4102.46,400.36 4135.8,400.36 4135.8,417.03 4152.46,417.03 4152.46,450.36 4135.8,450.36 4135.8,467.03 4102.46,467.03 4102.46,450.36 4085.8,450.36 4085.8,417.03 ; 4085.8,550.36 4085.8,567.03 4102.46,583.7 4085.8,600.36 4085.8,617.03 4102.46,617.03 4119.13,600.36 4135.8,617.03 4152.46,617.03 4152.46,600.36 4135.8,583.7 4152.46,567.03 4152.46,550.36 4135.8,550.36 4119.13,567.03 4102.46,550.36 4085.8,550.36 ; 4085.8,717.03 4102.46,717.03 4119.13,700.36 4135.8,717.03 4152.46,717.03 4135.8,733.7 4152.46,750.36 4135.8,750.36 4119.13,767.03 4102.46,750.36 4085.8,750.36 4102.46,733.7 4085.8,717.03 ; 4085.8,850.36 4119.13,867.03 4152.46,850.36 4135.8,883.7 4152.46,917.03 4119.13,900.36 4085.8,917.03 4102.46,883.7 4085.8,850.36 ; 5323.53,1689.59 5323.53,1789.59 6173.53,1789.59 6173.53,1689.59 5323.53,1689.59
  lines w15: 4026,-244.64 12903.54,-244.64 ; 4026,955.36 12903.54,955.36 ; 4576.88,-394.64 4576.88,1105.36 ; 5176.72,-394.64 5176.72,1105.36 ; 6326.38,-394.64 6326.38,1105.36 ; 6832.26,-394.64 6832.26,1105.36 ; 7566.06,-394.64 7566.06,1105.36 ; 9065.61,-394.64 9065.61,1105.36 ; 9655.46,-394.64 9655.46,1105.36 ; 10401.26,-394.64 10401.26,1105.36 ; 11500.94,-394.64 11500.94,1105.36 ; 4026,-394.64 12903.54,-394.64 12903.54,1105.36 4026,1105.36 4026,-394.64
  text "LAYER STACKUP DETAILS:" at 5323.53,2289.59 h60
  text "TOP SILKSCREEN" at 6223.53,2119.59 h40
  text "TOP SOLERMASK" at 6228.53,2019.59 h40
  text "TW - 8MIL, AIR GAP - 5MIL, COPLANAR SPACING - 6MIL 90 OHM IMPEDANCE" at 6512,1877 h40
  text "L01 TOP" at 6233.53,1874.59 h40
  text "1 OZ  MINIMUM (COPPER + PLATING)" at 4244.53,1863.59 h40
  text "L02 BOTTOM" at 6233.53,1569.59 h40
  text "1 OZ  MINIMUM (COPPER + PLATING)" at 4249.53,1568.59 h40
  text "BOTTOM SOLERMASK" at 6228.53,1434.59 h40
  text "BOTTOM SILKSCREEN" at 6223.53,1324.59 h40
  text "DRILL TOLERANCE : PTH +/- 3mil, NPTH +/- 2MIL" at 8320.5,1203.5 h60
  text "Symbol" at 4116,1000.36 h72
  text "Count" at 4621.88,1000.36 h72
  text "Hole Size" at 5221.72,1000.36 h72
  text "Plated" at 6371.38,1000.36 h72
  text "Hole Type" at 6877.26,1000.36 h72
  text "Drill Layer Pair" at 7611.06,1000.36 h72
  text "Via/Pad" at 9110.61,1000.36 h72
  text "Pad Shape" at 9700.46,1000.36 h72
  text "Hole Length" at 10446.26,1000.36 h72
  text "Routed Path Length" at 11545.94,1000.36 h72
  text "2" at 4621.88,850.36 h60
  text "19.69mil (0.500mm)" at 5221.72,850.36 h60
  text "PTH" at 6371.38,850.36 h60
  text "Slot" at 6877.26,850.36 h60
  text "Top Layer - Bottom Layer" at 7611.06,850.36 h60
  text "Pad" at 9110.61,850.36 h60
  text "Rounded" at 9700.46,850.36 h60
  text "45.28mil (1.150mm)" at 10446.26,850.36 h60
  text "25.59mil (0.650mm)" at 11545.94,850.36 h60
  text "2" at 4621.88,700.36 h60
  text "21.65mil (0.550mm)" at 5221.72,700.36 h60
  text "PTH" at 6371.38,700.36 h60
  text "Slot" at 6877.26,700.36 h60
  text "Top Layer - Bottom Layer" at 7611.06,700.36 h60
  text "Pad" at 9110.61,700.36 h60
  text "Rounded" at 9700.46,700.36 h60
  text "33.47mil (0.850mm)" at 10446.26,700.36 h60
  text "11.81mil (0.300mm)" at 11545.94,700.36 h60
  text "3" at 4621.88,550.36 h60
  text "39.00mil (0.991mm)" at 5221.72,550.36 h60
  text "NPTH" at 6371.38,550.36 h60
  text "Round" at 6877.26,550.36 h60
  text "Top Layer - Bottom Layer" at 7611.06,550.36 h60
  text "Pad" at 9110.61,550.36 h60
  text "Rounded" at 9700.46,550.36 h60
  text "-" at 10446.26,550.36 h60
  text "-" at 11545.94,550.36 h60
  text "3" at 4621.88,400.36 h60
  text "74.80mil (1.900mm)" at 5221.72,400.36 h60
  text "PTH" at 6371.38,400.36 h60
  text "Round" at 6877.26,400.36 h60
  text "Top Layer - Bottom Layer" at 7611.06,400.36 h60
  text "Pad" at 9110.61,400.36 h60
  text "Rounded" at 9700.46,400.36 h60
  text "-" at 10446.26,400.36 h60
  text "-" at 11545.94,400.36 h60
  text "4" at 4621.88,250.36 h60
  text "125.98mil (3.200mm)" at 5221.72,250.36 h60
  text "NPTH" at 6371.38,250.36 h60
  text "Round" at 6877.26,250.36 h60
  text "Top Layer - Bottom Layer" at 7611.06,250.36 h60
  text "Pad" at 9110.61,250.36 h60
  text "Rounded" at 9700.46,250.36 h60
  text "-" at 10446.26,250.36 h60
  text "-" at 11545.94,250.36 h60
  text "18" at 4621.88,100.36 h60
  text "10.10mil (0.257mm)" at 5221.72,100.36 h60
  text "PTH" at 6371.38,100.36 h60
  text "Round" at 6877.26,100.36 h60
  text "Top Layer - Bottom Layer" at 7611.06,100.36 h60
  text "Via" at 9110.61,100.36 h60
  text "Rounded" at 9700.46,100.36 h60
  text "-" at 10446.26,100.36 h60
  text "-" at 11545.94,100.36 h60
  text "32" at 4621.88,-49.64 h60
  text "39.37mil (1.000mm)" at 5221.72,-49.64 h60
  text "PTH" at 6371.38,-49.64 h60
  text "Round" at 6877.26,-49.64 h60
  text "Top Layer - Bottom Layer" at 7611.06,-49.64 h60
  text "Pad" at 9110.61,-49.64 h60
  text "(Mixed)" at 9700.46,-49.64 h60
  text "-" at 10446.26,-49.64 h60
  text "-" at 11545.94,-49.64 h60
  text "229" at 4621.88,-199.64 h60
  text "10.00mil (0.254mm)" at 5221.72,-199.64 h60
  text "PTH" at 6371.38,-199.64 h60
  text "Round" at 6877.26,-199.64 h60
  text "Top Layer - Bottom Layer" at 7611.06,-199.64 h60
  text "Via" at 9110.61,-199.64 h60
  text "Rounded" at 9700.46,-199.64 h60
  text "-" at 10446.26,-199.64 h60
  text "-" at 11545.94,-199.64 h60
  text "293 Total" at 4621.88,-349.64 h60
  text "'.Layer_Name'" at 923.75,-402.29 h60
  text "Slot definitions :" at 4116,-494.61 h60
  text "Routed Path Length" at 5148.69,-494.61 h60
  text "= Calculated from tool start centre position to tool end centre position." at 6251.36,-494.61 h60
  text "Hole Length" at 5148.69,-594.59 h60
  text "= Routed Path Length + Tool Size = Slot length as defined in the PCB layout" at 5841.49,-594.59 h60
Mechanical 18:
  circle w10: c-270.39,3103.76 r50
  circle w10: c-270.39,3103.76 r100
  circle w10: c3366.09,3103.15 r100
  circle w10: c3366.09,3103.15 r50
  circle w10: c-271.13,-640.9 r100
  circle w10: c-271.13,-640.9 r50
  lines w10: -421.13,-640.9 -121.13,-640.9 ; -420.39,3103.76 -120.39,3103.76 ; -271.13,-790.9 -271.13,-490.9 ; -270.39,2953.76 -270.39,3253.76 ; 3216.09,3103.15 3516.09,3103.15 ; 3366.09,2953.15 3366.09,3253.15
Mechanical 19:
  text "BOARD OUTLINE" at 342.25,-2328.29 h100
Mechanical 20:
  text "TOP ASSEMBLY" at 1682.25,-2308.29 h100
Mechanical 21:
  text "BOTTOM ASSEMBLY" at 1702.25,-2308.29 h100

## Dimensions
2700,1490 to 2600,1590 on Fabrication
2600,1590 to 2600,2040 on Fabrication
2700,1490 to 2700,200 on Fabrication
2600,100 to 2700,200 on Fabrication
2560,0 to 2600,100 on Fabrication
0,2060 to 2600,2040 on Fabrication
0,2060 to 2540,2100 on Fabrication
2560,40 to 2840,-210 on Fabrication
40,40 to -160,-130 on Fabrication
40,2060 to -160,2250 on Fabrication
40,0 to 40,2100 on Fabrication
0,40 to 2600,40 on Fabrication
0,40 to 2700,200 on Fabrication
